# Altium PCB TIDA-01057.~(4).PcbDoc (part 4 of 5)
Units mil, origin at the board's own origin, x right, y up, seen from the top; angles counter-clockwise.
Board outline 4448 x 3930 mil, 4 copper layers (Layer 1 - Top Layer, Layer 2 - GND, Layer 3 - PWR, Layer 4 - Bottom Layer), stack 59.034 mil thick; 537 components, 284 nets, 1540 pads, 770 vias.
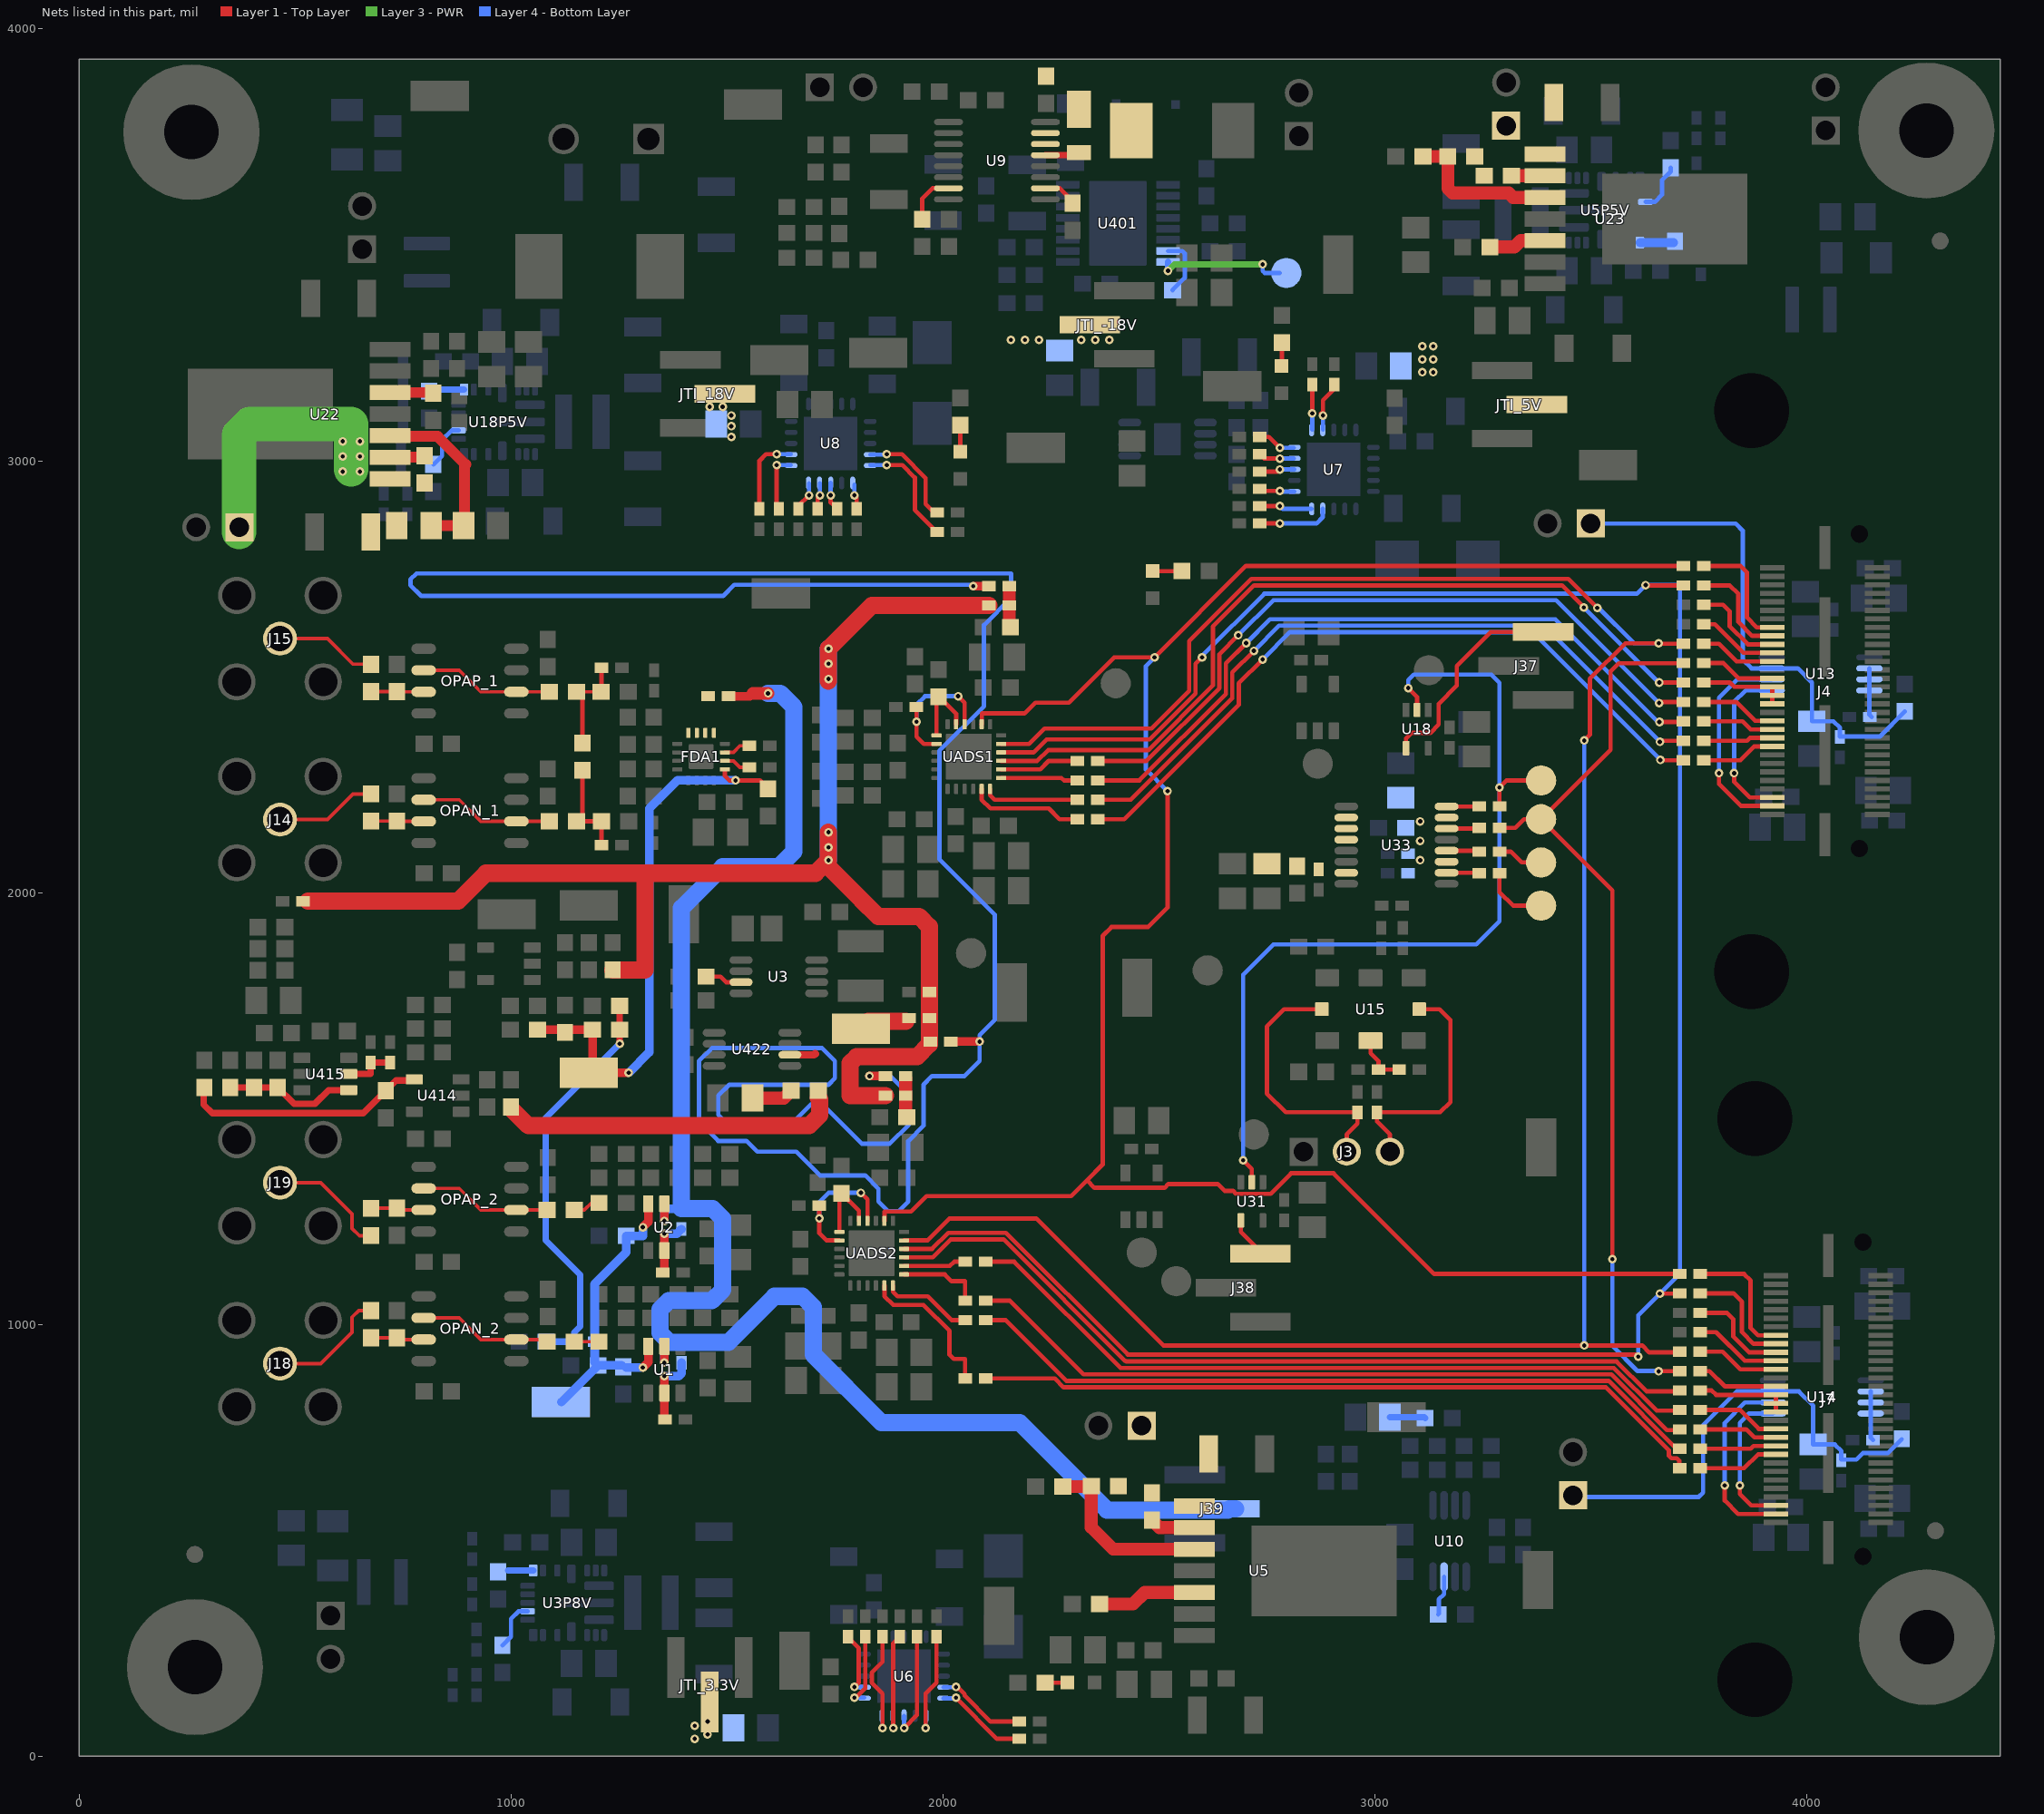
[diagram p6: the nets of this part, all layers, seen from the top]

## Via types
v1: diameter 20, hole 10, Layer 1 - Top Layer to Layer 4 - Bottom Layer, tented both sides, 382 vias
v2: diameter 20, hole 10, Layer 1 - Top Layer to Layer 4 - Bottom Layer, 258 vias
v3: diameter 20, hole 10, Layer 1 - Top Layer to Layer 4 - Bottom Layer, tented bottom, 57 vias
v4: diameter 19.68, hole 7.87, Layer 1 - Top Layer to Layer 4 - Bottom Layer, tented both sides, 48 vias
v5: diameter 20, hole 10, Layer 1 - Top Layer to Layer 4 - Bottom Layer, tented top, 19 vias
v6: diameter 19.68, hole 7.87, Layer 1 - Top Layer to Layer 4 - Bottom Layer, 6 vias

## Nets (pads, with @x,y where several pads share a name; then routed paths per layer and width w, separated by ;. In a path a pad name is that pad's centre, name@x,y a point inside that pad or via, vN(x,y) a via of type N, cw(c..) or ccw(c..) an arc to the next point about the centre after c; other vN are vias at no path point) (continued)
NetC460_2: C460.2 R494.1 U414.4 | length 571.6
  Layer 1 - Top Layer w15: R494.1@289.7,1548.5 288.2,1550 288.2,1508.8 308,1489 657.76,1489 C460.2@710,1541.24 733.5,1564.75 773.46,1564.75 U414.4@775.87,1567.15
NetC461_2: C461.2 R491.2 R492.1 U415.4 | length 310.8
  Layer 1 - Top Layer w15: R492.1@344.7,1542.95 R492.1@350.26,1548.5 ; R492.1@349.7,1548.5 R492.1@350.26,1548.5 ; U415.4@624.13,1542.34 577.6,1542.34 546.25,1511 496.95,1511 R491.2@459.7,1548.25 404.95,1548.25 C461.2@404.7,1548.5 R492.1@350.26,1548.5
NetCin1_1: Cin1.1 JZI_18V.1 Rent.2 Ron.2 U22.1 | length 600.4
  Layer 3 - PWR w80: JZI_18V.1@370,2835 370,3060 395,3085 630,3085 630,2980
  other v2: 610,2975 650,2975 610,3010 650,3010 610,3045 650,3045
NetCin2_1: Cin2.1 JZI_5V.1 Rent2.2 Ron2.2 U23.1
NetCin3_1: Cin3.1 JZI_3.3V.1 Rent3.2 Ron3.2 U5.1
NetCMFB_1: CMFB.1 RDP1.2 RDP2.2 RMFBP.2 | length 237.3
  Layer 1 - Top Layer w10: CMFB.1@1165,2283.25 1165,2178.25 RDP1.2@1151.5,2164.75 1209.25,2164.75 RDP2.2@1209.5,2165 1209.5,2110.13 RMFBP.2@1209.38,2110
NetCMFB_2: CMFB.2 RDN1.2 RDN2.2 RMFBN.1 | length 237.3
  Layer 1 - Top Layer w8: RDN1.2@1151.5,2464.75 RDN2.2@1208.5,2464.75 RDN2.2@1209.38,2465.62
  Layer 1 - Top Layer w10: RDN1.2@1151.5,2464.75 1165,2451.24 CMFB.2@1165,2346.24 ; RDN2.2@1209.38,2465.62 RMFBN.1@1209.38,2520.55
NetCR481_1: CR481.1 RR413.1 | length 96.5
  Layer 1 - Top Layer w30: CR481.1@1559,1524 1631.5,1524 RR413.1@1648.5,1541
NetCss2_1: Css2.1 U23.5 | length 134.1
  Layer 1 - Top Layer w30: Css2.1@3266.5,3495 3323,3495 3338,3510 U23.5@3394.37,3510
NetCss3_1: Css3.1 U5.5 | length 231.1
  Layer 1 - Top Layer w30: Css3.1@2362.5,352 2440,352 2467,379 U5.5@2582.37,379
NetCss_2: Css.2 U22.5 | length 98.9
  Layer 1 - Top Layer w25: U22.5@719.63,3158 Css.2@818.5,3158
NetCVCC3V_1: CVCC3V.1 U3P8V.1 | length 57.6
  Layer 4 - Bottom Layer w15: 993.62,429.8 U3P8V.1@1051.26,429.8
NetCVCC5V_1: CVCC5V.1 U5P5V.1 | length 82.6
  Layer 4 - Bottom Layer w10: CVCC5V.1@3691.69,3505.2 CVCC5V.1@3695,3508.5
  Layer 4 - Bottom Layer w20: U5P5V.1@3613.74,3505.2 CVCC5V.1@3691.69,3505.2
NetCVCC18V_1: CVCC18V.1 U18P5V.1 | length 82.6
  Layer 4 - Bottom Layer w15: CVCC18V.1@810,3161.5 813.31,3164.8 U18P5V.1@891.26,3164.8
NetD2_2: D2.2 U9.13 | length 80.3
  Layer 1 - Top Layer w10: D2.2@2308.99,3707.8 D2.2@2315,3713.8
  Layer 1 - Top Layer w14: U9.13@2237.2,3707.8 D2.2@2308.99,3707.8
NetD14_2: D14.2 R46.1 | length 52
  Layer 1 - Top Layer w10: R46.1@2236.5,170 D14.2@2288.5,170
NetD18_2: D18.2 R47.1 | length 67.7
  Layer 1 - Top Layer w10: D18.2@2486,2744.5 2553,2744.5 R47.1@2553.5,2745
NetD21_2: D21.2 R246.1 | length 54.5
  Layer 1 - Top Layer w10: D21.2@2783.32,3219.73 2785,3221.42 R246.1@2785,3273.5
NetD22_2: D22.2 R247.1 | length 61
  Layer 1 - Top Layer w10: D22.2@2040,3021.5 R247.1@2040,3082.52
NetFDA1_10: FDA1.10 R211.1 | length 62.5
  Layer 1 - Top Layer w8: FDA1.10@1495.12,2304.9 1514.84,2304.9 1530,2289.75 R211.1@1551.38,2289.75
NetFDA1_11: FDA1.11 R212.1 | length 62.5
  Layer 1 - Top Layer w8: FDA1.11@1495.12,2324.59 1514.84,2324.59 1530,2339.75 R212.1@1551.38,2339.75
NetFDA1_13: FDA1.13 FDA1.14 FDA1.15 FDA1.16 R248.1
NetJ4_16: J4.16 R65.2 | length 278.6
  Layer 1 - Top Layer w10: R65.2@3762.01,2756.39 3846.52,2756.39 3861.52,2741.39 3861.52,2636.88 3884.21,2614.19 J4.16@3920.51,2614.19
NetJ4_18: J4.18 R66.2 | length 245.4
  Layer 1 - Top Layer w10: R66.2@3761.36,2711.39 3821.52,2711.39 3841.52,2691.39 3841.52,2626.88 3873.91,2594.49 J4.18@3920.51,2594.49
NetJ4_20: J4.20 R67.2 | length 217.3
  Layer 1 - Top Layer w10: R67.2@3761.36,2666.39 3806.52,2666.39 3821.52,2651.39 3821.52,2616.88 3863.61,2574.79 J4.20@3920.51,2574.79
NetJ4_22: J4.22 R68.2 | length 186.6
  Layer 1 - Top Layer w10: R68.2@3761.36,2621.39 3787.01,2621.39 3853.31,2555.09 J4.22@3920.51,2555.09
NetJ4_24: J4.24 R69.2 | length 176.1
  Layer 1 - Top Layer w10: R69.2@3761.36,2576.39 3796.52,2576.39 3837.52,2535.39 J4.24@3920.51,2535.39
NetJ4_28: J4.28 R70.2 | length 173.8
  Layer 1 - Top Layer w10: R70.2@3761.36,2531.39 3807.01,2531.39 3842.41,2495.99 J4.28@3920.51,2495.99
NetJ4_30: J4.30 J4.32 J4.34 R71.2 | length 202.2
  Layer 1 - Top Layer w10: R71.2@3761.36,2486.39 3822.01,2486.39 3832.11,2476.29 J4.30@3920.02,2476.29 ; J4.34@3920.51,2436.89 J4.32@3920.51,2456.59 J4.30@3920.51,2476.29
NetJ4_38: J4.38 R72.2 | length 177.3
  Layer 1 - Top Layer w10: R72.2@3761.36,2441.39 3836.52,2441.39 3880.42,2397.49 J4.38@3920.51,2397.49
NetJ4_40: J4.40 R73.2 | length 166.8
  Layer 1 - Top Layer w10: R73.2@3761.36,2396.39 3851.52,2396.39 3870.12,2377.79 J4.40@3920.51,2377.79
NetJ4_42: J4.42 R74.2 | length 161.9
  Layer 1 - Top Layer w10: R74.2@3761.36,2351.39 3861.52,2351.39 3868.22,2358.09 J4.42@3920.51,2358.09
NetJ4_44: J4.44 R75.2 | length 172.4
  Layer 1 - Top Layer w10: R75.2@3761.36,2306.39 3846.52,2306.39 3878.52,2338.39 J4.44@3920.51,2338.39
NetJ7_16: J7.16 R76.2 | length 303.2
  Layer 1 - Top Layer w10: R76.2@3748.65,1116.69 3855.03,1116.69 3870.03,1101.69 3870.03,991.69 3887.23,974.49 J7.16@3928.52,974.49
NetJ7_18: J7.18 R77.2 | length 269.3
  Layer 1 - Top Layer w10: R77.2@3748.65,1071.69 3830.03,1071.69 3850.03,1051.69 3850.03,981.69 3876.93,954.79 J7.18@3928.52,954.79
NetJ7_20: J7.20 R78.2 | length 241.2
  Layer 1 - Top Layer w10: R78.2@3748.65,1026.69 3815.03,1026.69 3830.03,1011.69 3830.03,971.69 3866.63,935.09 J7.20@3928.52,935.09
NetJ7_22: J7.22 R79.2 | length 207.3
  Layer 1 - Top Layer w10: R79.2@3748.65,981.69 3790.03,981.69 3856.33,915.39 J7.22@3928.52,915.39
NetJ7_24: J7.24 R80.2 | length 196.9
  Layer 1 - Top Layer w10: R80.2@3748.65,936.69 3805.03,936.69 3846.03,895.69 J7.24@3928.52,895.69
NetJ7_28: J7.28 R81.2 | length 194.5
  Layer 1 - Top Layer w10: R81.2@3748.65,891.69 3775.03,891.69 3810.43,856.29 J7.28@3928.52,856.29
NetJ7_30: J7.30 J7.32 J7.34 R82.2 | length 223.5
  Layer 1 - Top Layer w10: R82.2@3748.65,846.69 3780.03,846.69 3790.13,836.59 J7.30@3928.52,836.59 J7.32@3928.52,816.89 J7.34@3928.52,797.19
NetJ7_38: J7.38 R83.2 | length 198.1
  Layer 1 - Top Layer w10: R83.2@3748.65,801.69 3845.03,801.69 3888.93,757.79 J7.38@3928.52,757.79
NetJ7_40: J7.40 R84.2 | length 187.6
  Layer 1 - Top Layer w10: R84.2@3748.65,756.69 3860.03,756.69 3878.63,738.09 J7.40@3928.52,738.09
NetJ7_42: J7.42 R85.2 | length 182.6
  Layer 1 - Top Layer w10: R85.2@3748.65,711.69 3870.03,711.69 3876.73,718.39 J7.42@3928.52,718.39
NetJ7_44: J7.44 R86.2 | length 193.1
  Layer 1 - Top Layer w10: R86.2@3748.65,666.69 3855.03,666.69 3887.03,698.69 J7.44@3928.52,698.69
NetJ37_1: J37.1 U18.4 | length 500.2
  Layer 1 - Top Layer w10: U18.4@3070.13,2332.17 U18.4@3072.22,2334.25 3072.22,2356.96 3085,2369.75 3128.38,2369.75 3147.81,2389.17 3147.81,2436.99 3190,2479.18 3190,2524.75 3268.74,2603.49 J37.1@3389.96,2603.49
NetJ38_1: J38.1 U31.4 | length 120.5
  Layer 1 - Top Layer w10: U31.4@2689.62,1240.45 2689.62,1214.26 2735.39,1168.49 J38.1@2764.96,1168.49
NetJTI_3.3V_2: JTI_3.3V.2 L19.1
  other v2: 1425,40 1455,50 1425,70 1455,80
NetJTI_5V_2: JTI_5V.2 L18.1
  other v2: 3110,3205 3135,3205 3110,3235 3135,3235 3110,3265 3135,3265
NetJTI_18V_2: JTI_18V.2 L16.2
  other v2: 1510,3055 1510,3080 1510,3105 1460,3125 1490,3125
NetJTI_-18V_2: JTI_-18V.2 L17.2
  other v2: 2157.5,3280 2190,3280 2222.5,3280 2320,3280 2352.5,3280 2385,3280
NetL5_2: L5.2 R22.2 | length 82.4
  Layer 4 - Bottom Layer w15: L5.2@3035,785 3114.52,785 R22.2@3116.52,783
NetOPAN_1_2: OPAN_1.2 OPAN_1.6 RDP1.1 | length 311.5
  Layer 1 - Top Layer w8: OPAN_1.2@797.71,2214.74 879.99,2214.74 929.99,2164.74 OPAN_1.6@1012.28,2164.74 RDP1.1@1088.5,2164.75
NetOPAN_2_2: OPAN_2.2 OPAN_2.6 RDP3.1 | length 301.5
  Layer 1 - Top Layer w8: OPAN_2.2@797.72,1014.75 880,1014.75 930,964.75 OPAN_2.6@1012.28,964.75 RDP3.1@1078.5,964.75
NetOPAP_1_2: OPAP_1.2 OPAP_1.6 RDN1.1 | length 311.5
  Layer 1 - Top Layer w8: OPAP_1.2@797.72,2514.75 880,2514.75 930,2464.75 OPAP_1.6@1012.28,2464.75 RDN1.1@1088.5,2464.75
NetOPAP_2_2: OPAP_2.2 OPAP_2.6 RDN3.1 | length 306.2
  Layer 1 - Top Layer w8: OPAP_2.2@797.72,1314.75 880,1314.75 930,1264.75 OPAP_2.6@1012.28,1264.75 RDN3.1@1083.19,1264.75
NetR3_2: R3.2 U3.3 | length 86.2
  Layer 1 - Top Layer w10: R3.2@1451.5,1805.16 1484.79,1805.16 1497.58,1792.36 U3.3@1532.4,1792.36
NetR8_2: R8.2 U8.4 | length 251.2
  Layer 1 - Top Layer w10: v1(1870,3015) 1905,3015 1960,2960 1960,2900 1980,2880 R8.2@1991.38,2880
  Layer 4 - Bottom Layer w10: U8.4@1831.54,3014.41 1869.41,3014.41 v1(1870,3015)
NetR9_2: R9.2 U8.5 | length 275.9
  Layer 1 - Top Layer w10: v1(1870,2990) 1906.1,2990 1935,2961.1 1935,2886.38 ; 1935,2893.05 1935,2886.38 ; R9.2@1985,2835 R9.2@1986.38,2835 ; R9.2@1991.38,2835 R9.2@1986.38,2835 ; 1935,2886.38 R9.2@1986.38,2835
  Layer 4 - Bottom Layer w10: U8.5@1831.54,2990 v1(1870,2990)
NetR10_2: R10.2 U8.6 | length 58.1
  Layer 1 - Top Layer w10: v1(1795,2920) 1800,2915 R10.2@1800,2888.62
  Layer 4 - Bottom Layer w10: v1(1795,2920) U8.6@1795,2944.65
NetR11_2: R11.2 U8.8 | length 66.1
  Layer 1 - Top Layer w10: v1(1740,2920) 1740,2903.62 R11.2@1755,2888.62
  Layer 4 - Bottom Layer w10: v1(1740,2920) U8.8@1740,2948.46
NetR12_2: R12.2 U8.9 | length 61.3
  Layer 1 - Top Layer w10: R12.2@1710,2888.62 1710,2915 v1(1715,2920)
  Layer 4 - Bottom Layer w10: v1(1715,2920) U8.9@1715,2947.87
NetR13_2: R13.2 U8.10 | length 69
  Layer 1 - Top Layer w10: R13.2@1665,2888.62 1665,2895 v1(1690,2920)
  Layer 4 - Bottom Layer w10: v1(1690,2920) U8.10@1690,2947.28
NetR14_2: R14.2 U8.11 | length 135.7
  Layer 1 - Top Layer w10: v1(1615,2990) 1615,2893.62 R14.2@1620,2888.62
  Layer 4 - Bottom Layer w10: v1(1615,2990) U8.11@1647.28,2990
NetR15_2: R15.2 U8.12 | length 190.5
  Layer 1 - Top Layer w10: R15.2@1575,2888.62 1575,3000 1590,3015 v1(1615,3015)
  Layer 4 - Bottom Layer w10: v1(1615,3015) U8.12@1647.87,3015
NetR17_2: R17.2 U7.4 | length 170.8
  Layer 1 - Top Layer w10: R17.2@2733.62,2855 v2(2780,2855)
  Layer 4 - Bottom Layer w10: v2(2780,2855) 2865,2855 2879.41,2869.41 U7.4@2879.41,2888.46
NetR18_2: R18.2 U7.5 | length 117.9
  Layer 1 - Top Layer w10: R18.2@2733.62,2895 v2@2775,2895
  Layer 4 - Bottom Layer w10: v2(2780,2895) 2786.54,2888.46 U7.5@2853.82,2888.46
NetR19_2: R19.2 U7.6 | length 75.3
  Layer 1 - Top Layer w10: R19.2@2738.62,2930 v1(2780,2930)
  Layer 4 - Bottom Layer w10: v1(2780,2930) 2781.18,2928.82 U7.6@2813.46,2928.82
NetR20_2: R20.2 U7.8 | length 81.9
  Layer 1 - Top Layer w10: R20.2@2733.62,2975 2775,2975 v1(2780,2980)
  Layer 4 - Bottom Layer w10: v1(2780,2980) U7.8@2813.46,2980
NetR21_2: R21.2 U10.3 | length 93
  Layer 4 - Bottom Layer w10: R21.2@3146.52,328 3148.02,329.5 3148.02,363 3160.22,375.2 U10.3@3160.22,415.32
NetR24_2: R24.2 U7.9 | length 69.3
  Layer 1 - Top Layer w10: R24.2@2743.62,3005 v1(2780,3005)
  Layer 4 - Bottom Layer w10: v1(2780,3005) U7.9@2812.87,3005
NetR25_2: R25.2 U7.10 | length 89
  Layer 1 - Top Layer w10: R25.2@2733.62,3055 2755,3055 v1(2780,3030)
  Layer 4 - Bottom Layer w10: v1(2780,3030) U7.10@2812.28,3030
NetR26_2: R26.2 U7.11 | length 103.7
  Layer 1 - Top Layer w10: v1(2855,3110) R26.2@2855,3176.38
  Layer 4 - Bottom Layer w10: U7.11@2855,3072.72 v1(2855,3110)
NetR27_2: R27.2 U7.12 | length 122.1
  Layer 1 - Top Layer w10: v1@2875,3110 v1(2880,3105) 2880,3140 2906,3166 R27.2@2906,3176.38
  Layer 4 - Bottom Layer w10: U7.12@2880,3072.13 v1(2880,3105)
NetR29_2: R29.2 U6.4 | length 209.3
  Layer 1 - Top Layer w10: v1(2030,160) 2035,155 2038.28,155 2050,143.28 2050,140 2110,80 R29.2@2176.38,80
  Layer 4 - Bottom Layer w10: U6.4@2001.54,159.41 v1@2029.41,159.41
NetR30_2: R30.2 U6.5 | length 214.7
  Layer 1 - Top Layer w10: v1(2030,135) 2125,40 R30.2@2176.38,40
  Layer 4 - Bottom Layer w10: U6.5@2001.54,133.82 2028.82,133.82 v1(2030,135)
NetR31_2: R31.2 U6.6 | length 249
  Layer 1 - Top Layer w10: v1(1960,65) 1960,145 1985,170 R31.2@1985,276.38
  Layer 4 - Bottom Layer w10: v1(1960,65) U6.6@1960,92.28
NetR32_2: R32.2 U6.8 | length 252.3
  Layer 1 - Top Layer w10: v1(1910,65) 1940,95 R32.2@1940,276.38
  Layer 4 - Bottom Layer w10: v1(1910,65) U6.8@1910,93.46
NetR33_2: R33.2 U6.9 | length 245.5
  Layer 1 - Top Layer w10: v1(1885,65) 1885,261.38 R33.2@1900,276.38
  Layer 4 - Bottom Layer w10: v1(1885,65) U6.9@1885,92.87
NetR34_2: R34.2 U6.10 | length 259.2
  Layer 1 - Top Layer w10: v1(1860,65) 1860,144.91 1835.16,169.75 1835.16,193.22 1860,218.06 R34.2@1860,276.38
  Layer 4 - Bottom Layer w10: v1(1860,65) U6.10@1860,92.28
NetR35_2: R35.2 U6.11 | length 176.1
  Layer 1 - Top Layer w10: v1(1795,135) 1798.28,135 1820.16,156.87 1820.16,276.22 R35.2@1820,276.38
  Layer 4 - Bottom Layer w10: v1(1795,135) U6.11@1817.28,135
NetR36_2: R36.2 U6.12 | length 153.7
  Layer 1 - Top Layer w10: R36.2@1780,276.38 1780,274.68 1805,249.68 1805,170 v1(1795,160)
  Layer 4 - Bottom Layer w10: v1(1795,160) U6.12@1817.87,160
NetR50_2: R50.2 U9.7 | length 118.6
  Layer 1 - Top Layer w10: R50.2@1952.22,3559.06 1952.22,3607.22 1976.02,3631.02 U9.7@2012.8,3631.02
NetR90_2: R90.2 R91.2 U15.2@2990,1656.91 | length 122.6
  Layer 1 - Top Layer w10: U15.2@2990,1656.91 2990,1627.75 3008.62,1609.12 R91.2@3008.62,1589.75 R90.2@3056.38,1589.75
NetR95_1: R95.1 U33.16 | length 75.4
  Layer 1 - Top Layer w10: U33.16@3166.14,2199.31 3240.95,2199.31 R95.1@3241.38,2199.75
NetR223_1: R223.1 UADS2.17 | length 349
  Layer 1 - Top Layer w10: UADS2.17@1864.53,1089.94 1864.53,1065.22 1885,1044.75 1955,1044.75 2015,984.75 2015,929.75 2025,919.75 2051.38,919.75 R223.1@2051.38,874.75
NetR225_1: R225.1 UADS2.19 | length 193.1
  Layer 1 - Top Layer w10: UADS2.19@1909.8,1115.53 2004.21,1115.53 2020,1099.75 2051.38,1099.75 R225.1@2051.38,1054.75
NetR226_1: R226.1 UADS2.20 | length 145.6
  Layer 1 - Top Layer w10: UADS2.20@1909.8,1135.22 2016.01,1135.22 2025.79,1145 R226.1@2051.38,1145
NetR232_1: R232.1 UADS1.17 | length 265.4
  Layer 1 - Top Layer w10: UADS1.17@2089.53,2239.94 2089.53,2215.22 2110,2194.75 2245,2194.75 2270,2169.75 R232.1@2311.38,2169.75
NetR233_1: R233.1 UADS1.18 | length 221
  Layer 1 - Top Layer w10: UADS1.18@2109.21,2239.94 2109.21,2225.53 2120,2214.75 R233.1@2311.38,2214.75
NetR234_1: R234.1 UADS1.19 | length 179
  Layer 1 - Top Layer w10: UADS1.19@2134.8,2265.53 2274.21,2265.53 2280,2259.75 R234.1@2311.38,2259.75
NetR235_1: R235.1 UADS1.20 | length 184.7
  Layer 1 - Top Layer w10: UADS1.20@2134.8,2285.22 2225.47,2285.22 2245,2304.75 R235.1@2311.38,2304.75
NetR240_1: R240.1 UADS2.18 | length 208.8
  Layer 1 - Top Layer w10: UADS2.18@1884.21,1089.94 1884.21,1075.53 1895,1064.75 1965,1064.75 2020,1009.75 R240.1@2051.38,1009.75
NetR250_2: R250.2 REN0.2 U1.5 | length 165.9
  Layer 1 - Top Layer w20: REN0.2@1355,781.12 U1.5@1355,840.61 v1(1355,879.75)
  Layer 4 - Bottom Layer w20: v1(1355,879.75) 1388,879.75 1395,886.75 R250.2@1395,911.12
NetR252_2: R252.2 REN1.2 U2.5 | length 135.4
  Layer 1 - Top Layer w20: REN1.2@1351.38,1119.75 1355,1123.37 U2.5@1355,1170.61 v1(1355,1209.75)
  Layer 4 - Bottom Layer w20: v1(1355,1209.75) 1383.84,1209.75 R252.2@1394.48,1220.39
NetR256_1: R256.1 U33.14 | length 75.9
  Layer 1 - Top Layer w10: U33.14@3166.14,2148.13 3239.76,2148.13 R256.1@3241.38,2149.75
NetR257_1: R257.1 U33.12 | length 76.2
  Layer 1 - Top Layer w10: U33.12@3166.14,2096.95 3239.18,2096.95 R257.1@3241.38,2094.75
NetR258_2: R258.2 R259.2 R260.2 | length 91.2
  Layer 1 - Top Layer w30: R260.2@2153.62,2704.75 R259.2@2153.62,2664.75 2153.62,2617.62 R258.2@2156.5,2614.75
NetR261_2: R261.2 R262.1 R263.1 | length 87.1
  Layer 1 - Top Layer w30: R261.2@1913.62,1482.62 R263.1@1913.62,1569.75
NetR278_1: R278.1 U33.10 | length 75.7
  Layer 1 - Top Layer w10: U33.10@3166.14,2045.77 3240.36,2045.77 R278.1@3241.38,2044.75
NetR279_2: R279.2 U13.2 U13.3 U13.4 | length 115
  Layer 4 - Bottom Layer w10: U13.2@4145.2,2519.19 U13.3@4145.2,2493.6 U13.4@4145.2,2468.01 4145.2,2411.83 R279.2@4150.63,2406.39
NetR280_2: R280.2 U14.2 U14.3 U14.4 | length 115
  Layer 4 - Bottom Layer w10: U14.2@4148.21,844.49 U14.3@4148.21,818.9 U14.4@4148.21,793.31 4148.21,737.13 R280.2@4153.65,731.69
NetR284_2: R284.2 UADS1.4 UADS1.8 | length 337.8
  Layer 1 - Top Layer w10: R284.2@1938.62,2429.75 v1(1938.62,2395.43) 1938.62,2361.12 1955.47,2344.27 UADS1.8@1985.2,2344.27 ; v1(2035,2454.75) 2050.16,2439.59 UADS1.4@2050.16,2389.55
  Layer 4 - Bottom Layer w10: v1(1938.62,2395.43) 1938.62,2435.02 1958.35,2454.75 v1(2035,2454.75)
NetR288_2: R288.2 UADS2.4 UADS2.8 | length 331.8
  Layer 1 - Top Layer w10: R288.2@1713.62,1274.75 v1(1713.62,1245.43) 1713.62,1211.12 1730.47,1194.27 UADS2.8@1760.2,1194.27 ; v1(1810,1304.75) 1825.16,1289.59 UADS2.4@1825.16,1239.55
  Layer 4 - Bottom Layer w10: v1(1713.62,1245.43) 1713.62,1283.37 1735,1304.75 v1(1810,1304.75)
NetR404_2: R404.2 U401.7 | length 138.2
  Layer 4 - Bottom Layer w10: U401.7@2521.14,3486.02 2553.98,3486.02 2560,3480 2560,3423.5 R404.2@2531.5,3395
NetR453_2: R453.2 R454.2 U415.5 | length 122.2
  Layer 1 - Top Layer w15: U415.5@624.13,1579.75 675,1579.75 R453.2@675,1606.12 R454.2@720,1606.12
NetRDN3_2: RDN3.2 RDN4.2 | length 64.1
  Layer 1 - Top Layer w8: RDN3.2@1146.18,1264.75 1169.75,1264.75 1186,1281 RDN4.2@1203.5,1281
NetRDP3_2: RDP3.2 RDP4.2 | length 57
  Layer 1 - Top Layer w8: RDP3.2@1146.5,959.75 RDP4.2@1203.5,959.75
NetRenb2_2: Renb2.2 Rent2.1 U23.3 | length 365
  Layer 1 - Top Layer w30: Renb2.2@3111.5,3705 Rent2.1@3168.5,3705 ; Rent2.1@3169.15,3705 3169.15,3630.85 3180,3620 3310,3620 3320,3610 U23.3@3394.37,3610
NetRenb3_2: Renb3.2 Rent3.1 U5.3 | length 421.7
  Layer 1 - Top Layer w30: Renb3.2@2277.5,624 2342.5,624 Rent3.1@2343.5,625 2343.5,529.5 2394,479 U5.3@2582.37,479
NetRenb_2: Renb.2 Rent.1 U22.3 | length 422.4
  Layer 1 - Top Layer w25: U22.3@719.63,3058 719.63,3056.32 830,3056.32 895,2991.32 892.5,2988.82 892.5,2852.5 Renb.2@890,2850 Rent.1@815,2850
NetRES3V_2: RES3V.2 U3P8V.19 | length 115.4
  Layer 4 - Bottom Layer w10: RES3V.2@980,256.5 1000,276.5 1000,317.95 1017.36,335.32 U3P8V.19@1038.46,335.32
NetRES5V_2: RES5V.2 U5P5V.19 | length 115.9
  Layer 4 - Bottom Layer w10: U5P5V.19@3626.54,3599.69 3648.47,3599.69 3665,3616.21 3665,3650 3685,3670 RES5V.2@3685,3678.5
NetRES18V_2: RES18V.2 U18P5V.19 | length 112.7
  Layer 4 - Bottom Layer w10: RES18V.2@820,2991.5 840,3011.5 840,3048.32 862,3070.31 U18P5V.19@878.46,3070.31
NetRon2_1: Ron2.1 U23.2 | length 77.9
  Layer 1 - Top Layer w30: Ron2.1@3316.5,3660 U23.2@3394.37,3660
NetRon3_1: Ron3.1 U5.2 | length 105.6
  Layer 1 - Top Layer w30: Ron3.1@2484,546.5 2501.5,529 U5.2@2582.37,529
NetRon_1: Ron.1 U22.2 | length 76.9
  Layer 1 - Top Layer w25: U22.2@719.63,3008 Ron.1@796.5,3008
NetTPPGOOD_1: TPPGOOD.1 U401.8 | length 302.6
  Layer 3 - PWR w15: v2(2521.14,3440) 2536.14,3455 v2(2740,3455)
  Layer 4 - Bottom Layer w10: v2(2740,3455) 2740,3440 2745,3435 TPPGOOD.1@2780,3435
  Layer 4 - Bottom Layer w15: v2(2521.14,3440) U401.8@2521.14,3460.43
NISO_SCL_DIF: J4.58 U13.6 | length 483.4
  Layer 1 - Top Layer w10: v1(3797.01,2276.39) 3797.01,2251.39 3847.91,2200.49 J4.58@3920.02,2200.49
  Layer 4 - Bottom Layer w10: v1(3797.01,2276.39) 3797.01,2451.39 3839.21,2493.6 U13.6@3918.82,2493.6
NISO_SCL_SERI: J7.58 U14.6 | length 442.7
  Layer 1 - Top Layer w10: v1(3810.02,626.69) 3810.02,591.69 3840.93,560.79 J7.58@3928.52,560.79
  Layer 4 - Bottom Layer w10: v1(3810.02,626.69) 3810.02,771.69 3857.23,818.9 U14.6@3921.84,818.9
NISO_SDA_DIF: J4.56 U13.5 | length 386.3
  Layer 1 - Top Layer w10: v1(3832.01,2276.39) 3832.01,2256.39 3868.21,2220.19 J4.56@3920.51,2220.19
  Layer 4 - Bottom Layer w10: v1(3832.01,2276.39) 3832.01,2441.39 3858.62,2468.01 U13.5@3918.82,2468.01
NISO_SDA_SERI: J7.56 U14.5 | length 345.1
  Layer 1 - Top Layer w10: v1(3845.02,626.69) 3845.02,606.69 3871.23,580.49 J7.56@3928.52,580.49
  Layer 4 - Bottom Layer w10: v1(3845.02,626.69) 3845.02,771.69 3866.64,793.31 U14.5@3921.84,793.31
OPAN1_N: C72.2 OPAP_1.3 R98.2 | length 122
  Layer 1 - Top Layer w8: R98.2@676,2465.5 C72.2@736,2465.5 736.76,2464.75 OPAP_1.3@797.72,2464.75
OPAN1_P: C71.2 OPAN_1.3 R97.2 | length 121
  Layer 1 - Top Layer w8: R97.2@677,2165.5 C71.2@736,2165.5 736.76,2164.74 OPAN_1.3@797.71,2164.74
OPAN2_N: C97.2 OPAP_2.3 R108.2 | length 123.9
  Layer 1 - Top Layer w8: R108.2@675.7,1268.5 676.05,1268.84 C97.2@735.7,1268.84 739.8,1264.75 OPAP_2.3@797.72,1264.75
OPAN2_P: C96.2 OPAN_2.3 R107.2 | length 130.6
  Layer 1 - Top Layer w5: R107.2@668.7,968.5 R107.2@673.7,968.5
  Layer 1 - Top Layer w8: R107.2@673.7,968.5 R107.2@676,968.5 C96.2@736,968.5 739.76,964.75 OPAN_2.3@797.72,964.75
PRE: C40.1 D2.1 L1.1 U9.14 U9.15
REFBUF_DIF: C322.1 UADS1.5 UADS1.7 | length 165
  Layer 1 - Top Layer w10: UADS1.7@1985.2,2364.75 C322.1@1985.2,2448.45 ; C322.1@1990,2453.25 1991.5,2453.25 2030.47,2414.27 UADS1.5@2030.47,2389.55
REFBUF_SE: C323.1 UADS2.5 UADS2.7 | length 171
  Layer 1 - Top Layer w10: UADS2.7@1760.2,1214.75 1760.2,1298.45 C323.1@1765,1303.25 1805.47,1262.78 UADS2.5@1805.47,1239.55
REFOUT: R485.1 RR413.2 RR457.2 TPV4.1 U422.6 | length 951.5
  Layer 1 - Top Layer w17: U422.6@1645.6,1624.2 1701.55,1624.2 ; 1704.29,1626.95 1705,1626.24
  Layer 1 - Top Layer w40: R485.1@1005,1494.75 1040,1459.75 1690,1459.75 1715,1484.75 1715,1521.24 RR413.2@1711.5,1524.75 ; TPV4.1@1805,1679.75 TPV4.1@1810,1684.75 1827,1701.75 RR457.2@1914.12,1701.75
RVS_DIF: R71.1 UADS1.21 | length 1923.4
  Layer 1 - Top Layer w10: UADS1.21@2134.8,2304.9 2218.38,2304.9 2243.22,2329.75 2475.15,2329.75 2625,2479.6 2625,2616.11 2720.29,2711.39 3433.61,2711.39 3484,2661 v2(3484,2660) ; v2(3658.61,2486.39) R71.1@3714.12,2486.39 R71.1@3712.73,2487.78
  Layer 4 - Bottom Layer w10: v2(3484,2660) 3657.61,2486.39 v2(3658.61,2486.39)
RVS_SE: R82.1 UADS2.21 | length 1960.3
  Layer 1 - Top Layer w10: UADS2.21@1909.8,1154.9 1976.37,1154.9 2018.23,1196.77 2140.02,1196.77 2421.79,915 2423,915 2424,914 3559.85,914 3628.85,845 3704.71,845 R82.1@3706.4,846.69
SCL: J3.3 R89.1 U15.8 | length 556.1
  Layer 1 - Top Layer w10: J3.3@3035,1399.75 3035,1439.75 3005,1469.75 R89.1@3005,1491.12 3151.38,1491.12 3175,1514.75 3175,1704.75 3150,1729.75 U15.8@3102.8,1729.75
SCLK_PHI: R69.1 R80.1 UADS1.23 UADS2.23 | length 5559.9
  Layer 1 - Top Layer w10: UADS2.23@1909.8,1194.27 1964.53,1194.27 2015.25,1245 2216.21,1245 2510.21,951 v2(3485,951) 3619,951 3635,935 3704.71,935 R80.1@3706.4,936.69 ; UADS1.23@2134.8,2344.27 2199.53,2344.27 2235,2379.75 2482.72,2379.75 2570,2467.02 2570,2582.32 2714.07,2726.39 3447.82,2726.39 3515,2659.21 v2(3515,2659) ; v2(3485,2352) 3498,2365 3498,2495 3580,2577 v2(3657,2577) 3657.61,2576.39 R69.1@3714.12,2576.39 R69.1@3711.72,2578.79
  Layer 4 - Bottom Layer w10: v2(3485,951) v2(3485,2352) ; v2(3515,2659) 3518,2659 3600,2577 v2(3657,2577)
SDA: J3.2 R88.1 U15.7 | length 628.6
  Layer 1 - Top Layer w10: U15.7@2877.2,1729.75 2790,1729.75 2750,1689.75 2750,1534.75 2793.62,1491.12 R88.1@2960,1491.12 2960,1464.75 2935,1439.75 J3.2@2935,1399.75
SDI: R66.1 R77.1 UADS1.22 UADS2.22 | length 5567.1
  Layer 1 - Top Layer w10: UADS2.22@1909.8,1174.59 1974.84,1174.59 2012.25,1212 2146,1212 2428,930 3605,930 v2(3610,925) ; UADS1.22@2134.8,2324.59 2209.84,2324.59 2240,2354.75 2478.93,2354.75 2585,2460.81 2585,2529.75 v2(2600,2544.75) ; v2(3627,2712) 3627.61,2711.39 R66.1@3714.12,2711.39 R66.1@3713.51,2712 ; v2(3660,1071) 3705.71,1071 R77.1@3706.4,1071.69 R77.1@3706.35,1071.75
  Layer 4 - Bottom Layer w10: v2(2600,2544.75) 2600,2547.89 2744.11,2692 3607,2692 v2(3627,2712) 3699.29,2712 3706.4,2704.89 3706.4,1116.69 3705.69,1116.69 v2(3660,1071) 3610,1021 v2(3610,925)
SDO0_DIF: R72.1 R235.2 | length 1658
  Layer 1 - Top Layer w10: R235.2@2358.62,2304.75 2471.36,2304.75 2640,2473.39 2640,2551.84 v2(2683.95,2595.79) ; v2(3658,2439) 3660.39,2441.39 R72.1@3714.12,2441.39 R72.1@3712.12,2439.4
  Layer 4 - Bottom Layer w10: v2(2683.95,2595.79) 2765.16,2677 3420,2677 v2(3658,2439)
SDO0_SE: R83.1 R226.2 | length 1751.5
  Layer 1 - Top Layer w10: R226.2@2098.62,1145 2165,1145 2411,899 3553.64,899 3652.64,800 3704.71,800 R83.1@3706.4,801.69 R83.1@3706.35,801.75
SDO1_DIF: R73.1 R234.2 | length 1650.9
  Layer 1 - Top Layer w10: R234.2@2358.62,2259.75 2455,2259.75 2655,2459.75 2655,2530.79 v2(2701.98,2577.77) ; v2(3659,2395) 3712.73,2395 R73.1@3714.12,2396.39
  Layer 4 - Bottom Layer w10: v2(2701.98,2577.77) 2757.21,2633 3418,2633 3656,2395 v2(3659,2395)
SDO1_SE: R84.1 R225.2 | length 1732.7
  Layer 1 - Top Layer w10: R225.2@2098.62,1054.75 2155,1054.75 2325.75,884 3547.43,884 3676.43,755 3704.71,755 R84.1@3706.4,756.69 R84.1@3706.35,756.75
SDO2_DIF: R74.1 R233.2 | length 1672.9
  Layer 1 - Top Layer w10: R233.2@2358.62,2214.75 2435,2214.75 2670,2449.75 2670,2509.75 v2(2720,2559.75) ; v2(3660,2349) 3662.39,2351.39 R74.1@3714.12,2351.39 R74.1@3712.12,2349.4
  Layer 4 - Bottom Layer w10: v2(2720,2559.75) 2778.25,2618 3391,2618 v2(3660,2349)
SDO2_SE: R85.1 R240.2 | length 1732.6
  Layer 1 - Top Layer w10: R240.2@2098.62,1009.75 2145,1009.75 2285.75,869 3541.21,869 3700.21,710 3704.71,710 R85.1@3706.4,711.69
SDO3_DIF: R75.1 R232.2 | length 1687.1
  Layer 1 - Top Layer w10: R232.2@2358.62,2169.75 2420,2169.75 2685,2434.75 2685,2484.75 v2(2740,2539.75) ; v2(3661,2307) 3661.61,2306.39 R75.1@3714.12,2306.39
  Layer 4 - Bottom Layer w10: v2(2740,2539.75) 2803.25,2603 3365,2603 v2(3661,2307)
SDO3_SE: R86.1 R223.2 | length 1723.1
  Layer 1 - Top Layer w10: R223.2@2105,868.37 R223.2@2098.62,874.75 2258.79,874.75 2279.53,854 3535,854 3680.66,708.34 3680.66,695.74 3686.51,689.88 3699.12,689.88 3704.71,684.29 3704.71,665 R86.1@3706.4,666.69
SRESETN: R65.1 R76.1 UADS1.2 UADS2.2 | length 5187.7
  Layer 1 - Top Layer w10: UADS2.2@1864.53,1239.55 1865,1240.02 1865,1261.36 1926.25,1261.36 1961.89,1297 2297,1297 2333.5,1333.5 ; UADS1.2@2089.53,2389.55 2090,2390.02 2090,2414.75 2188.79,2414.75 2213.79,2439.75 2291.36,2439.75 2396.36,2544.75 v2(2490,2544.75) 2701.65,2756.39 R65.1@3714.12,2756.39 ; v2(2520,2234.75) 2520,1965 2475,1920 2390,1920 2370,1900 2370,1370 2333.5,1333.5 ; R76.1@3706.4,1116.69 3137.41,1116.69 2904.36,1349.75 2806.07,1349.75 2758.63,1302.3 2678.76,1302.3 2672.03,1309.04 2651.93,1309.04 2636.22,1324.75 2521.72,1324.75 2513.27,1316.3 2350.7,1316.3 2333.5,1333.5
  Layer 4 - Bottom Layer w10: v2(2490,2544.75) 2470,2524.75 2470,2284.75 v2(2520,2234.75)
SS: C34.1 U9.10 | length 82.1
  Layer 1 - Top Layer w10: U9.10@2237.2,3631.02 2270.47,3631.02 C34.1@2305,3596.5
SYSCLK0: R95.2 TP16.1 U18.2 U31.2 | length 2139.3
  Layer 1 - Top Layer w10: v1(2695,1379.75) 2715.21,1359.53 U31.2@2715.21,1329.04 ; v1(3077.6,2473.54) 3097.81,2453.33 U18.2@3097.81,2422.84 ; R95.2@3288.63,2199.75 v1(3288.63,2243.37) 3305,2259.75 3375,2259.75 TP16.1@3385,2269.75
  Layer 4 - Bottom Layer w10: v1(2695,1379.75) 2695,1809.75 2765,1879.75 3235,1879.75 3288.63,1933.37 v1(3288.63,2243.37) 3288.63,2486.12 3270,2504.75 3090,2504.75 3077.6,2492.34 v1(3077.6,2473.54)
SYSCLK1: R70.1 R81.1 R256.2 TP31.1 | length 2159
  Layer 1 - Top Layer w10: R256.2@3288.63,2149.75 3325,2149.75 3345,2169.75 TP31.1@3385,2169.75 ; v2(3550,1151) 3550,2004.75 TP31.1@3385,2169.75 ; v2(3657,891) 3657.69,891.69 R81.1@3706.4,891.69 ; R70.1@3714.12,2531.39 3713.73,2531 3565,2531 3546,2512 3546,2330.75 TP31.1@3385,2169.75
  Layer 4 - Bottom Layer w10: v2(3550,1151) 3550,950 3608,892 3656,892 v2(3657,891)
SYSCLK2: R257.2 TP32.1 | length 106.7
  Layer 1 - Top Layer w10: R257.2@3288.63,2094.75 3315,2094.75 3340,2069.75 TP32.1@3385,2069.75
SYSCLK3: R278.2 TP33.1 | length 153
  Layer 1 - Top Layer w10: R278.2@3288.63,2044.75 3288.63,2001.12 3320,1969.75 TP33.1@3385,1969.75
V_CM: C84.1 FDA1.9 R214.2 R215.2 R216.2 TP29.1 | length 1301
  Layer 1 - Top Layer w10: FDA1.9@1495.12,2283.75 1495.12,2269.63 1505,2259.75 v1(1520,2259.75) 1576.5,2259.75 C84.1@1586.5,2249.75
  Layer 1 - Top Layer w20: R216.2@1061.5,1682.38 1118.5,1682.38 R215.2@1125,1675.88 1131.5,1682.38 R214.2@1188.5,1682.38 1188.5,1590.88 TP29.1@1180,1582.38 v1(1272.37,1582.38)
  Layer 4 - Bottom Layer w20: v1(1272.37,1582.38) 1320,1630.01 1320,2194.75 1385,2259.75 v1(1520,2259.75)
V_CM_OPA: C108.1 C318.1 R213.1 R214.1 | length 952.3
  Layer 1 - Top Layer w15: v1(1251.5,1649.75) R214.1@1251.5,1682.38 C318.1@1251.5,1737.38
  Layer 4 - Bottom Layer w15: C108.1@1081.5,959.75 R213.1@1146.38,959.75 1146.38,981.12 1160,994.75 1160,1114.75 1080,1194.75 1080,1478.25 v1(1251.5,1649.75)
V_REF_OPA0: C109.1 C115.1 R110.2 R213.2 TP30.1 U1.3 U2.3 | length 725.8
  Layer 1 - Top Layer w20: v1(1305,899.75) 1317.6,912.34 U1.3@1317.6,948.88 ; v1(1305,1224.75) 1317.6,1237.34 U2.3@1317.6,1278.88
  Layer 4 - Bottom Layer w10: TP30.1@1115,819.75 TP30.1@1116.5,819.75 ; R110.2@1193.62,912.62 R110.2@1201.5,904.75 ; C109.1@1256.5,904.75 C109.1@1260,901.24
  Layer 4 - Bottom Layer w20: TP30.1@1116.5,819.75 R110.2@1201.5,904.75 C109.1@1256.5,904.75 ; R110.2@1193.62,912.62 R213.2@1193.62,959.75 1193.62,1093.37 1266.5,1166.24 C115.1@1266.5,1204.75 1305,1204.75 v1(1305,1224.75) ; C109.1@1266.5,899.75 v1(1305,899.75)
VDD: C339.1 C340.1 L10.1 U33.2 U33.3 U33.4 U33.7
VDDO: C348.1 C349.1 C350.1 L12.1 U33.11 U33.15
  other v1: 3105,2074.75 3105,2119.75 3105,2164.75
VEE: J39.2 R248.2 R250.1 R252.1 U1.2 U2.2 | length 3850.7
  Layer 1 - Top Layer w20: v1(1355,911.12) U1.2@1355,948.88 ; v1(1355,1239.43) U2.2@1355,1278.88 ; R248.2@1503.62,2454.75 1553.5,2454.75 1560,2461.24
  Layer 1 - Top Layer w30: 1560,2461.24 v1(1595,2461.24)
  Layer 4 - Bottom Layer w20: v1(1355,911.12) 1355,946.99 1366.38,958.37 ; v1(1355,1239.43) 1355,1259.75 1362.89,1267.63 R252.1@1394.48,1267.63
  Layer 4 - Bottom Layer w40: v1(1595,2461.24) 1623.5,2461.24 1655,2429.75 1655,2094.75 1620,2059.75 1490,2059.75 1394.48,1964.23 R252.1@1394.48,1267.63 1467.11,1267.63 1490,1244.75 1490,1079.75 1465,1054.75 1365,1054.75 1345,1034.75 1345,979.75 1366.38,958.37 1503.62,958.37 1610,1064.75 1675,1064.75 1700,1039.75 1700,929.75 1857.25,772.5 2177.5,772.5 2380,570 2659.98,570 J39.2@2662.98,573 J39.2@2678.02,573
VIN+_1_N: J15.1 R98.1 | length 235.6
  Layer 1 - Top Layer w8: J15.1@465,2588 575,2588 634,2529 675.5,2529 R98.1@676,2528.5
VIN+_1_P: J14.1 R97.1 | length 235.6
  Layer 1 - Top Layer w8: J14.1@465,2169 575,2169 634,2228 675.5,2228 R97.1@676,2228.5
VIN+_2_N: J19.1 R108.1 | length 281.5
  Layer 1 - Top Layer w8: J19.1@465,1328 559.47,1328 632,1255.47 632,1222 649,1205 675.2,1205 R108.1@675.7,1205.5
VIN+_2_P: J18.1 R107.1 | length 280.7
  Layer 1 - Top Layer w8: J18.1@465,909 559.47,909 632,981.53 ; 632,983.53 632,1016.54 647.46,1032 675.5,1032 R107.1@676,1031.5
VREF: R56.2 R218.2 R255.2 R259.1 R262.2 R457.2 RR457.1 | length 3524.6
  Layer 1 - Top Layer w20: R218.2@1235,1820.88 R218.2@1235.66,1820.22
  Layer 1 - Top Layer w40: R457.2@530,1979.75 877.14,1979.75 942.14,2044.75 ; 941.49,2044.75 942.14,2044.75 ; R218.2@1235.66,1820.22 1310,1820.22 1310,2044.75 ; v1(1735,2139.75) v1(1735,2104.75) v1(1735,2074.75) ; v1@1735,2489.75 v1(1735,2494.75) v1(1735,2529.75) v1(1735,2564.75) 1835,2664.75 R259.1@2106.38,2664.75 ; 1849.82,1944.57 1810,1984.39 1810,1984.75 1735,2059.75 v1(1735,2074.75) ; 1850,1944.75 1945,1944.75 1968.62,1921.12 R56.2@1968.62,1769.75 1968.62,1648.37 1940,1619.75 1800,1619.75 1785,1604.75 1785,1529.75 R262.2@1866.38,1529.75 ; 942.14,2044.75 1310,2044.75 ; 1310,2044.75 1705,2044.75 v1(1735,2074.75)
  Layer 4 - Bottom Layer w40: v1(1735,2074.75) v1(1735,2104.75) v1(1735,2139.75) v1(1735,2494.75) v1(1735,2529.75) v1(1735,2564.75)
VREF1: R255.1 R260.1 R263.2 | length 6729
  Layer 1 - Top Layer w20: v1(1830,1574.75) R263.2@1866.38,1574.75 ; R255.1@2018.62,1654.75 v1(2085,1654.75) ; v1(2070,2709.75) R260.1@2106.38,2709.75
  Layer 4 - Bottom Layer w10: v1(1830,1574.75) 1878.19,1574.75 1921.05,1531.88 1921.05,1462.26 1877.05,1418.25 1811.5,1418.25 1720,1509.75 1695,1509.75 1650,1464.75 1500,1464.75 1480,1484.75 1480,1529.75 1505,1554.75 1735,1554.75 1750,1569.75 1750,1609.75 1720,1639.75 1465,1639.75 1435,1609.75 1435,1469.3 1479.55,1424.75 1545,1424.75 1570,1399.75 1660,1399.75 1715,1344.75 1820,1344.75 1850.57,1314.17 1850.57,1284.17 1872.55,1262.2 1897.45,1262.2 1919.45,1284.19 1919.45,1424.43 1955,1459.98 1955,1554.75 1975,1574.75 2050,1574.75 2085,1609.75 v1(2085,1654.75) 2085,1669.75 2120,1704.75 2120,1949.39 1991.85,2077.54 1991.85,2328.29 2095,2431.44 2095,2619.75 2094.84,2619.75 2157.67,2682.57 2157.67,2739 781,2739 767,2725 767,2712 792,2687 1490.97,2687 1516.72,2712.75 2067,2712.75 v1(2070,2709.75)
WP1_0: C54.2 C262.1 J5.1 R64.1 U13.7 | length 1196.8
  Layer 4 - Bottom Layer w10: J5.1@3500,2855 3500.6,2854.4 3835.6,2854.4 3852.01,2837.99 3852.01,2539.19 3872.01,2519.19 U13.7@3918.82,2519.19 3979.22,2519.19 4012.01,2486.39 C262.1@4012.01,2396.39 4062.01,2396.39 4077.01,2381.39 4077.01,2361.39 4169.8,2361.39 R64.1@4227.66,2419.25 ; R64.1@4227.01,2418.61 R64.1@4227.01,2419.9
WP1_1: C56.2 C261.1 J6.1 R87.1 U14.7 | length 1105.1
  Layer 4 - Bottom Layer w10: J6.1@3459,604 3463,600 3750,600 3760,610 3760,766.67 3837.82,844.49 U14.7@3921.84,844.49 3982.23,844.49 4015.02,811.69 C261.1@4015.02,721.69 4065.03,721.69 4080.03,706.69 4080.03,686.7 4115.03,686.7 4130.02,701.69 4187.81,701.69 R87.1@4220.03,733.91
pads on no net: FID1.1 FID2.1 FID3.1 FID4.1 FID5.1 FID6.1 H1.1 H2.1 H3.1 H4.1 H9. H11. H13. H15. J4.2 J4.3 J4.4 J4.5 J4.6 J4.7 J4.8 J4.9 J4.10 J4.11 J4.12 J4.13 J4.14 J4.15 J4.17 J4.19 J4.21 J4.23 J4.25 J4.26 J4.27 J4.29 J4.31 J4.33 J4.35 J4.36 J4.37 J4.39 J4.41 J4.43 J4.45 J4.46 J4.47 J4.48 J4.49 J4.51 J4.52 J4.53 J4.54 J4.55 J4.57 J4.MH1 J4.MH2 J7.2 J7.3 J7.4 J7.5 J7.6 J7.7 J7.8 J7.9 J7.10 J7.11 J7.12 J7.13 J7.14 J7.15 J7.17 J7.19 J7.21 J7.23 J7.25 J7.26 J7.27 J7.29 J7.31 J7.33 J7.35 J7.36 J7.37 J7.39 J7.41 J7.43 J7.45 J7.46 J7.47 J7.48 J7.49 J7.51 J7.52 J7.53 J7.54 J7.55 J7.57 J7.MH1 J7.MH2 OPAN_1.1 OPAN_1.5 OPAN_1.8 OPAN_2.1 OPAN_2.5 OPAN_2.8 OPAP_1.1 OPAP_1.5 OPAP_1.8 OPAP_2.1 OPAP_2.5 OPAP_2.8 U3P8V.3 U3P8V.4A U3P8V.4B U3P8V.8A U3P8V.8B U3P8V.9A U3P8V.9B U3P8V.9C U3P8V.9D U3P8V.10A U3P8V.10B U3P8V.14A U3P8V.14B U5P5V.3 U5P5V.4A U5P5V.4B U5P5V.8A U5P5V.8B U5P5V.9A U5P5V.9B U5P5V.9C U5P5V.9D U5P5V.10A U5P5V.10B U5P5V.14A U5P5V.14B U9.2 U9.4 U11.3 U11.7 U15.1@2874.25,1656.91 U15.1@2905.75,1656.91 U15.2@2974.25,1656.91 U15.2@3005.75,1656.91 U15.3@3074.25,1656.91 U15.3@3105.75,1656.91 U15.4@3074.25,1802.58 U15.4@3105.75,1802.58 U15.5@2974.25,1802.58 U15.5@3005.75,1802.58 U15.6@2874.25,1802.58 U15.6@2905.75,1802.58 U18P5V.3 U18P5V.4A U18P5V.4B U18P5V.8A U18P5V.8B U18P5V.9A U18P5V.9B U18P5V.9C U18P5V.9D U18P5V.10A U18P5V.10B U18P5V.14A U18P5V.14B U19.1 U32.1 U33.8 U401.17@2405,3550 U422.1 U422.3 U422.5 U422.7 U422.8 UADS1.6 UADS2.6

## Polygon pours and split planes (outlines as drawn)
-18V on Layer 3 - PWR "-18V_L03_P203" (solid, remove dead copper, pour order 203): 263,1101 263,843 330,776 1393,776 1393,1555 1207,1741 928,1741 883,1786 883,1821 933,1871 1376.37,1871 1413,1907.63 1413,2427.79 1569.48,2427.79 1593,2451.31 1593,2501 1628,2536 1908,2536 1908,2735 1437,2735 1258,2556 1258,2552.65 1258,2236 1203,2181 903,2181 863,2221 863,2336 838,2361 458,2361 458,2146 458,1550.99 1153.01,1550.99 1262.75,1441.25 1262.75,1032.25 1261.5,1031 1211.5,981 1204.38,981 898,981 853,1026 853,1136 768,1221 433.18,1221 433.18,1101
5V on Layer 3 - PWR "5V_L03_P202" (solid, remove dead copper, pour order 202): 2212,2712.56 1941.26,2712.56 1941.26,2509.09 1656.26,2509.09 1626.26,2479.09 1626.26,2435.09 1591.26,2400.09 1333,2400.09 1333,1842.56 946.26,1842.57 916.26,1812.57 916.26,1807.56 916.26,1783.88 946.26,1753.88 1181.12,1753.88 1413,1522 1413,776 1981.26,776 1981.26,991.93 1852,1035 1852,1276.59 1981.25,1322.02 1981.25,1483.25 2028,1530 2212,1530 2212,2168 2072,2168 2072,2432.98 2212,2470.38
+18V on Layer 3 - PWR "+18V_L03_P204" (solid, remove dead copper, pour order 204): 1188,2726 1233,2681 1233,2245.04 1188.96,2201 913.62,2201 883,2231.62 883,2346 848,2381 716.39,2381 681.39,2346 433,2346 433,1531 1144.5,1531 1243,1432.5 1243,1276 1203,1236 1203,1181 1243,1141 1243,1045.98 1198.02,1001 913,1001 873,1041 873,1156 793,1236 630.01,1236 630.01,1121 573.12,1121 573.12,1236 413,1236 413,1111 263,1111 263,2726
3.3V on Layer 3 - PWR "3.3V_L03_P206" (solid, remove dead copper, pour order 206): 1698,621 2058,621 2058,1456 2298,1456 2298,1754 2298,2801 2543,3046 3471.66,3046 4273,3046 4273,771 4273,296 3158,296 3003,296 2803,296 2401,296 2227.46,122.46 1698,122.46
AGND on Layer 2 - GND "AGND_L02_P200" (solid, remove dead copper, pour order 200): 229,867 326,770 610,770 1996,770 1996,995.69 1862,1043.69 1862,1112 1896.22,1112 1896.22,1214.6 1862,1214.6 1862,1269 1996,1316.2 1996,1478 2037,1519 2223,1519 2223,2093.44 2223,2181.69 2081,2181.69 2081,2267 2125,2267 2125,2359 2081,2359 2081,2426 2223,2465.25 2223,2532.25 2223,2745 510.02,2745 375.02,2880 229,2880 229,2485
GND on Layer 2 - GND "GND_L02_P201" (solid, remove dead copper, pour order 201): 17,2924 388,2924 522.05,2789.96 2268,2790.95 2268,2431.04 2159,2400.32 2159,2227 2268,2227 2268,1474 2057,1474 2046,1463 2046,1284.45 1935,1243 1935,1070 2046,1025.55 2046,725 542,725 306,489 17,489 17,8.95 4427,9.01 4427,3919 17,3919
AGND on Layer 1 - Top Layer "AGND_L01_P249" (solid, remove dead copper, pour order 249): 454.83,1938.3 454.83,1799.75 534.83,1799.75 534.83,1620.06 535.88,1619.02 579.83,1619.02 579.83,1938.3
GND on Layer 1 - Top Layer "GND_L01_P195" (solid, pour order 195): 2927,3278 2927,3208 2840,3208 2840,3278
GND on Layer 1 - Top Layer "GND_L01_P194" (solid, pour order 194): 2095,2990 2020,2990 2020,2815 2095,2815
+24VDC_IN on Layer 1 - Top Layer "+24VDC_IN_L01_P190" (solid, pour order 190): 755,3355 755,3890 985,3890 1172.5,3890 1172.5,3355
GND on Layer 1 - Top Layer "GND_L01_P193" (solid, pour order 193): 1640,3870 1245,3870 1245,3622.89 1640,3622.89 1640,3647.89 1787.27,3647.89 1787.27,3690 1640,3690
GND on Layer 1 - Top Layer "GND_L01_P196" (solid, pour order 196): 2705,3115 2615,3115 2615,2840 2705,2840 2705,3080
GND on Layer 1 - Top Layer "GND_L01_P197" (solid, pour order 197): 2005,305 2003.9,306.1 1385,306.1 1385,395 1722.6,395 1769.6,348 2005.5,348
GND on Layer 1 - Top Layer "GND_L01_P198" (solid, pour order 198): 2205,18.35 2246.85,18.35 2248,19.5 2248,125 2230,125 2205,100
GND on Layer 1 - Top Layer "GND_L01_P199" (solid, pour order 199): 1820,2870 1820,2810 1440,2810 1440,2870
-0.2V on Layer 1 - Top Layer "-0.2V_L01_P192" (solid, pour order 192): 2870,828.39 3031.52,828.39 3031.52,738.39 2870,738.39
NetC381_1 on Layer 4 - Bottom Layer "NETC381_1_L04_P228" (solid, remove dead copper, pour order 228): 995.2,3030 939.96,3030 939.96,2830 994.95,2830
GND on Layer 4 - Bottom Layer "GND_L04_P245" (solid, remove dead copper, pour order 245): 783.06,60.01 1085.25,60.3 1085.25,278.23 1015,278.23 1015,270.49 955,270.49 875,270.49 875,530 783.06,530
GND on Layer 4 - Bottom Layer "GND_L04_P240" (solid, remove dead copper, pour order 240): 3500,3550 3500,3480 3482.5,3480 3482.5,3290 2915,3290 2915,3890 3490,3890 3490,3610 3280,3610 3280,3550 3403.54,3550
GND on Layer 4 - Bottom Layer "GND_L04_P239" (solid, remove dead copper, pour order 239): 3585,3619.37 3585,3855 3905,3855 3905,3405 3790,3405 3790,3660 3815,3660 3815,3810 3723.35,3810 3723.35,3775 3650,3775 3650,3619.37
NetC369_1 on Layer 4 - Bottom Layer "NETC369_1_L04_P224" (solid, pour order 224): 3995,3920 3495,3920 3495,3695 3580,3695 3580,3860 3905,3860 3905,3400 3585,3400 3585,3480 3490,3480 3490,3290 3995,3290
GND on Layer 4 - Bottom Layer "GND_L04_P236" (solid, pour order 236): 2175,474.98 2175,513 2628.02,513 2628.02,474.98
5.5V on Layer 4 - Bottom Layer "5.5V_L04_P212" (solid, pour order 212): 2945,3090 2945,3060 2985,3020 3075,3020 3075,3152.4 3072.4,3155 2945,3155
5V on Layer 4 - Bottom Layer "5V_L04_P211" (solid, pour order 211): 2980,2935 3070,2935 3070,2850 3105,2815 3105,2715 2970,2715 2895,2715 2895,2905 2915,2905 2915,2865 2945,2865 2945,2905 2975,2935
GND on Layer 4 - Bottom Layer "GND_L04_P233" (solid, pour order 233): 2840,3010 2840,2945 2840,2920 2970,2920 2970,2945 3140,2945 3145,2940 3150,2935 3150,2780 3150,2750 3188,2712 3298.54,2712 3298.54,3091.46 3220,3170 3150,3170 3150,3063.68 3095,3063.68 3095,3010 2970,3010 2970,3040 2840,3040
+24VDC on Layer 4 - Bottom Layer "+24VDC_L04_P216" (solid, pour order 216): 1280,3560 1525,3560 1525,3310 1315,3310 1310,3315 1280,3345 1280,3505
18.5V on Layer 4 - Bottom Layer "18.5V_L04_P214" (solid, pour order 214): 1535,3025 1535,3255 1695,3255 1695,3262.5 1750,3262.5 1750,3220 1735,3205 1710,3205 1695,3190 1695,3150 1695,3115 1675,3115 1665,3105 1665,3085 1600,3085 1600,3025
GND on Layer 4 - Bottom Layer "GND_L04_P232" (solid, pour order 232): 1705,2980 1775,2980 1800,2980 1800,3100 1775,3100 1775,3160 1775,3170 1800,3195 1800,3255 2050,3255 2050,3365 1707.6,3365 1667.6,3325 1622.6,3325 1622.6,3280 1765,3280 1765,3210 1735,3180 1705,3180 1705,3100 1682.21,3100 1682.21,2980
+18V on Layer 4 - Bottom Layer "+18V_L04_P213" (solid, pour order 213): 1785,3115 1785,3155 1820,3190 2025,3190 2025,3035 1815,3035 1815,3050 1855,3050 1855,3080 1820,3080 1815,3085
GND on Layer 4 - Bottom Layer "GND_L04_P234" (solid, pour order 234): 1875,120 1945,120 1970,120 1970,250 1945,250 1945,425 1955,435 2061.26,435 2070,435 2095,410 2190,410 2190,535 1720,535 1720,430.43 1809.37,430.43 1809.37,390.63 1820,380 1858.7,380 1875,380 1875,245 1852.21,245 1852.21,120
3.8V on Layer 4 - Bottom Layer "3.8V_L04_P210" (solid, pour order 210): 1570,25 1735,25 1780,70 1780,180 1780,230 1825,230 1855,260 1855,270 1865,280 1868.54,283.54 1868.54,360 1731.06,360 1730.63,359.57 1715,343.94 1715,180 1715,176 1644,105 1570,105
3.3V on Layer 4 - Bottom Layer "3.3V_L04_P208" (solid, pour order 208): 1955,350 2065,350 2085,330 2190,330 2190,186.65 2178.35,175 2025,175 2025,195 2025,225 2020,230 1985,230 1985,250 1975,260 1955,260 1955,315
GND on Layer 4 - Bottom Layer "GND_L04_P230" (solid, pour order 230): 3103.02,736.68 3013.02,736.68 3013.02,660 2859.52,660 2859.52,579.5 2858.02,578 3013.02,578 3028.02,593 3103.02,593 3118.02,578 3118.02,548 3143.02,548 3143.02,618 3103.02,618
NetC357_1 on Layer 4 - Bottom Layer "NETC357_1_L04_P223" (solid, pour order 223): 705,615 1170,615 1170,575 1170,460 1106,460 1106,530 785,530 785,58 1090,58 1090,255 1165,255 1165,15 675,15 675,143.16 705,160
GND on Layer 4 - Bottom Layer "GND_L04_P235" (solid, pour order 235): 690,517 690,627 456,627 447,618 447,517 515,517
GND on Layer 4 - Bottom Layer "GND_L04_P238" (solid, pour order 238): 790,3744.97 560,3745.01 560,3927.8 762.2,3927.8 790,3900
GND on Layer 4 - Bottom Layer "GND_L04_P241" (solid, remove dead copper, pour order 241): 915,2926 915,2970 848.54,2970 848.54,2926 705,2926 705,3315 590,3315 590,2825 915,2825
NetC381_1 on Layer 4 - Bottom Layer "NETC381_1_L04_P225" (solid, remove dead copper, pour order 225): 1010,3170 1010,3440 377.93,3440 377.93,2957.07 505,2830 580,2830 580,3300 860,3300 935,3225 935,3205 935,3170
GND on Layer 4 - Bottom Layer "GND_L04_P243" (solid, remove dead copper, pour order 243): 1005,3050 1225,3050 1225,3105 1090,3105 1010,3105 1010,3400 1020,3410 1590,3410 1590,3180 1590,2940.58 1475,2830 1005,2830 1005,2915
NetC404_2 on Layer 4 - Bottom Layer "NETC404_2_L04_P227" (solid, remove dead copper, pour order 227): 2491.56,3915 2491.56,3751.42 2491.56,3616.78 2488.92,3616.78 2487.82,3615.67 2487.82,3606.78 2560.18,3606.78 2626.21,3606.78 2638.55,3606.78 2638.54,3710 2560.18,3710 2560.18,3782.8 2560.18,3915
GND on Layer 4 - Bottom Layer "GND_L04_P247" (solid, remove dead copper, pour order 247): 2128.54,3590 2130,3591.46 2130,3735 2447.97,3735 2447.97,3910 2075,3910 1940,3775 1940,3675 1940,3590
NetC403_2 on Layer 4 - Bottom Layer "NETC403_2_L04_P226" (solid, remove dead copper, pour order 226): 2485,3724.51 2485,3366.46 2571.46,3366.46 2575,3370 2575,3455 2658.54,3455 2660,3456.46 2660,3575 2725,3575 2710,3560 2710,3310 2200,3310 2200,3465 2105,3465 2105,3390 2105,3375 2370,3375 2370,3445 2335,3445 2335,3610 2145,3610 2146.16,3611.16 2146.16,3724.51
GND on Layer 4 - Bottom Layer "GND_L04_P229" (solid, remove dead copper, pour order 229): 1170,320 1240,320 1240,300 1400,300 1400,415 1240,415 1240,385 1170,385 1170,615 1710,615 1710,190 1625,105 1439.75,108.55 1295,80 1170,80 1170,105

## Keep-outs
Keep-Out Layer:
  text ".Layer_Name" at 57,-1078.49 h60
